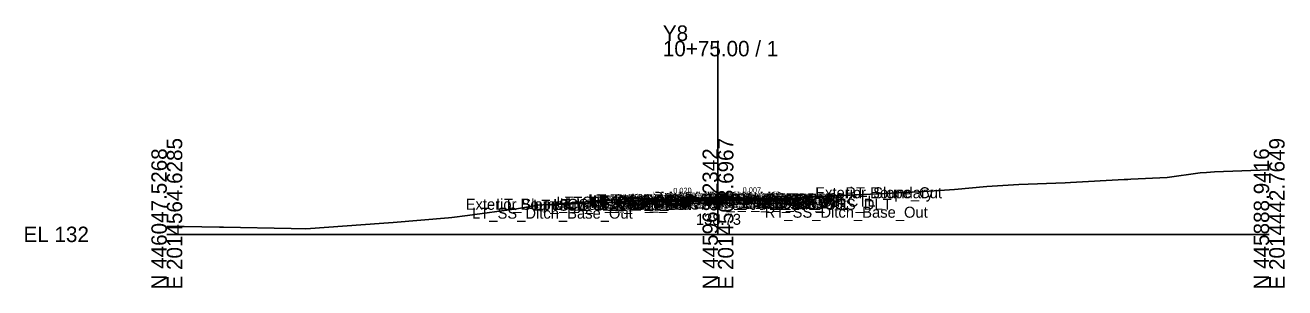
# Model space of a CAD drawing. Extents: x -26 to 1403, y -10 to 8043.
# Drawn here: x -25.7 to 202.8, y 1490.3 to 1537.9 of the extents above; entities that cross this region are included whole.
import ezdxf

# ---------------------------------------------------------------- set-up
doc = ezdxf.new("R2010")
doc.units = 0
for name, color, linetype in [('Default', 7, 'Continuous'), ('Exist CMT Pavement', 7, 'Continuous'), ('Exist Cross Section Cell', 7, 'Continuous'), ('Exist XS Center Line Elevation Label', 7, 'Continuous'), ('Exist XS Ground Line', 7, 'Continuous'), ('Prop CMT Pvmt Course 1', 7, 'Continuous'), ('Prop CMT Pvmt Course 2', 7, 'Continuous'), ('Prop CMT Pvmt Course 3', 7, 'Continuous'), ('Prop CMT Pvmt Surface', 7, 'Continuous'), ('Prop CMT Pvmt Surface Shoulder', 7, 'Continuous'), ('Prop CMT Pvmt Wedge Surface 1', 7, 'Continuous'), ('Prop CMT Pvmt Wedge Surface 2', 7, 'Continuous'), ('Prop CMT Pvmt Wedge Surface 3', 7, 'Continuous'), ('Prop CMT Shld Paved Course 1', 7, 'Continuous'), ('Prop CMT Shld Paved Course 2', 7, 'Continuous'), ('Prop CMT Shld Paved Course 3', 7, 'Continuous'), ('Prop CMT Slope Grass', 7, 'Continuous'), ('Prop CMT Subgrade Earthwork', 7, 'Continuous'), ('Prop XS Earthwork Shape', 7, 'Continuous'), ('Prop XS SE Text', 7, 'Continuous'), ('Scratch_Level_0', 7, 'Continuous')]:
    doc.layers.add(name, color=color, linetype=linetype)

msp = doc.modelspace()

# ---------------------------------------------------------------- linework, layer by layer
at = {"layer": 'Exist CMT Pavement'}
msp.add_lwpolyline([(89.09, 1506.27), (93.48, 1506.44), (100, 1506.73), (100.47, 1506.75), (108.36, 1506.51), (110.86, 1506.43)], dxfattribs=at)
at = {"layer": 'Exist Cross Section Cell'}
for p, q in [((100, 1500), (100, 1535.1)), ((0, 1500), (100, 1500)), ((100, 1500), (200, 1500))]:
    msp.add_line(p, q, dxfattribs=at)
at = {"layer": 'Exist XS Ground Line'}
msp.add_lwpolyline([(0, 1501.45), (3.18, 1501.42), (9.54, 1501.33), (10.31, 1501.32), (22.55, 1501.05), (25.21, 1500.99), (39.37, 1502.04), (41.09, 1502.15), (51.1, 1503), (51.73, 1503.09), (54.58, 1503.42), (63.47, 1504.63), (67.38, 1505.27), (75.95, 1505.89), (78.83, 1506.12), (80.74, 1506.23), (84.07, 1506.5), (86.2, 1506.44), (87.21, 1506.46), (88.1, 1506.47), (89.06, 1506.48), (89.09, 1506.27), (93.48, 1506.44), (100, 1506.73), (100.47, 1506.75), (108.36, 1506.51), (110.86, 1506.43), (112.44, 1506.52), (118.36, 1506.88), (122.64, 1507.05), (136.49, 1507.69), (142.92, 1508.12), (148.79, 1508.67), (154.59, 1509.05), (163.02, 1509.37), (163.95, 1509.39), (173.68, 1509.95), (174.36, 1509.98), (174.88, 1510.03), (181.49, 1510.31), (187.49, 1511.16), (188.62, 1511.21), (190.09, 1511.34), (200, 1511.7)], dxfattribs=at)
at = {"layer": 'Prop CMT Pvmt Course 1'}
for points in [[(100, 1506.58), (87.31, 1506.33)], [(87.31, 1506.33), (87.31, 1506.08)], [(87.31, 1506.08), (100, 1506.33)], [(100, 1506.58), (112.45, 1506.5)], [(100, 1506.58), (100, 1506.33)], [(112.45, 1506.25), (100, 1506.33)], [(112.45, 1506.5), (112.45, 1506.25)]]:
    msp.add_lwpolyline(points, dxfattribs=at)
at = {"layer": 'Prop CMT Pvmt Course 2'}
for points in [[(100, 1506.33), (87.31, 1506.08)], [(87.31, 1505.83), (100, 1506.08)], [(87.31, 1506.08), (87.31, 1505.83)], [(100, 1506.33), (112.45, 1506.25)], [(100, 1506.33), (100, 1506.08)], [(112.45, 1506), (100, 1506.08)], [(112.45, 1506.25), (112.45, 1506)]]:
    msp.add_lwpolyline(points, dxfattribs=at)
at = {"layer": 'Prop CMT Pvmt Course 3'}
for points in [[(100, 1506.08), (87.31, 1505.83)], [(100, 1506.08), (112.45, 1506)], [(100, 1506.08), (100, 1505.71)], [(87.31, 1505.83), (87.31, 1505.45)], [(87.31, 1505.45), (100, 1505.71)], [(112.45, 1505.62), (100, 1505.71)], [(112.45, 1506), (112.45, 1505.62)]]:
    msp.add_lwpolyline(points, dxfattribs=at)
at = {"layer": 'Prop CMT Pvmt Surface'}
for points in [[(100, 1506.58), (87.31, 1506.33)], [(100, 1506.58), (112.45, 1506.5)]]:
    msp.add_lwpolyline(points, dxfattribs=at)
at = {"layer": 'Prop CMT Pvmt Surface Shoulder'}
for points in [[(87.31, 1506.33), (87.31, 1506.33)], [(100, 1506.58), (100, 1506.58)], [(112.45, 1506.5), (112.45, 1506.5)]]:
    msp.add_lwpolyline(points, dxfattribs=at)
at = {"layer": 'Prop CMT Pvmt Wedge Surface 1'}
for points in [[(100, 1506.33), (87.31, 1506.08)], [(87.31, 1506.08), (87.31, 1506.33)], [(100, 1506.33), (112.45, 1506.25)], [(112.45, 1506.25), (112.45, 1506.5)]]:
    msp.add_lwpolyline(points, dxfattribs=at)
at = {"layer": 'Prop CMT Pvmt Wedge Surface 2'}
for points in [[(87.31, 1506.08), (87.31, 1506.33)], [(112.45, 1506.25), (112.45, 1506.5)]]:
    msp.add_lwpolyline(points, dxfattribs=at)
at = {"layer": 'Prop CMT Pvmt Wedge Surface 3'}
for points in [[(87.31, 1505.83), (87.31, 1506.33)], [(112.45, 1506), (112.45, 1506.5)]]:
    msp.add_lwpolyline(points, dxfattribs=at)
at = {"layer": 'Prop CMT Shld Paved Course 1'}
for points in [[(87.31, 1506.33), (87.06, 1506.07)], [(87.06, 1506.07), (87.31, 1506.08)], [(87.31, 1506.33), (87.31, 1506.33)], [(87.31, 1506.08), (87.31, 1506.33)], [(100, 1506.58), (100, 1506.58)], [(100, 1506.33), (100, 1506.58)], [(112.45, 1506.5), (112.45, 1506.5)], [(112.45, 1506.5), (112.7, 1506.24)], [(112.45, 1506.25), (112.45, 1506.5)], [(112.7, 1506.24), (112.45, 1506.25)]]:
    msp.add_lwpolyline(points, dxfattribs=at)
at = {"layer": 'Prop CMT Shld Paved Course 2'}
for points in [[(87.31, 1506.08), (87.06, 1506.07), (86.8, 1505.82)], [(87.31, 1505.83), (87.31, 1506.08)], [(100, 1506.08), (100, 1506.33)], [(112.45, 1506.25), (112.7, 1506.24), (112.96, 1505.99)], [(112.45, 1506), (112.45, 1506.25)], [(86.8, 1505.82), (87.31, 1505.83)], [(112.96, 1505.99), (112.45, 1506)]]:
    msp.add_lwpolyline(points, dxfattribs=at)
at = {"layer": 'Prop CMT Shld Paved Course 3'}
for points in [[(100, 1505.71), (100, 1506.08)], [(85.92, 1505.43), (87.31, 1505.45)], [(87.31, 1505.83), (86.8, 1505.82), (86.42, 1505.44)], [(87.31, 1505.45), (87.31, 1505.83)], [(112.45, 1505.62), (112.45, 1506)], [(112.45, 1506), (112.96, 1505.99), (113.34, 1505.61)], [(113.84, 1505.6), (112.45, 1505.62)]]:
    msp.add_lwpolyline(points, dxfattribs=at)
at = {"layer": 'Prop CMT Slope Grass'}
for p, q in [((112.45, 1506.5), (126.23, 1507.22)), ((81.31, 1505.85), (68.76, 1505.37))]:
    msp.add_line(p, q, dxfattribs=at)
msp.add_lwpolyline([(87.31, 1506.33), (81.31, 1505.85)], dxfattribs=at)
at = {"layer": 'Prop CMT Subgrade Earthwork'}
msp.add_line((114.87, 1506.63), (113.84, 1505.6), dxfattribs=at)
for points in [[(85.92, 1505.43), (81.31, 1505.85)], [(87.31, 1505.45), (85.92, 1505.43)], [(100, 1505.71), (87.31, 1505.45)], [(100, 1505.71), (112.45, 1505.62)], [(112.45, 1505.62), (113.84, 1505.6)]]:
    msp.add_lwpolyline(points, dxfattribs=at)
at = {"layer": 'Prop XS Earthwork Shape'}
for points in [[(89.09, 1506.27), (93.48, 1506.44), (93.79, 1506.46), (100, 1506.58), (107.62, 1506.53), (108.36, 1506.51), (110.86, 1506.43), (112.13, 1506.5), (118.36, 1506.88), (126.23, 1507.22), (114.87, 1506.63), (113.84, 1505.6), (112.45, 1505.62), (100, 1505.71), (87.31, 1505.45), (85.92, 1505.43), (81.31, 1505.85), (68.76, 1505.37), (75.95, 1505.89), (80.74, 1506.23), (84.07, 1506.5), (86.2, 1506.44), (87.21, 1506.46), (89.06, 1506.48)], [(89.09, 1506.27), (93.48, 1506.44), (93.79, 1506.46), (89.08, 1506.36)], [(100, 1506.58), (107.62, 1506.53), (100.47, 1506.75), (100, 1506.73), (93.79, 1506.46)], [(110.86, 1506.43), (112.13, 1506.5), (107.62, 1506.53), (108.36, 1506.51)]]:
    msp.add_lwpolyline(points, close=True, dxfattribs=at)

# ---------------------------------------------------------------- texts
at = {"layer": 'Default'}
msp.add_text('-', height=0.0001, dxfattribs=at).set_placement((0, 1500))
at = {"layer": 'Exist Cross Section Cell'}
for s, p in [('Y8', (90, 1535.1)), ('10+75.00 / 1', (90, 1532.3)), ('EL 132', (-26, 1498.6))]:
    msp.add_text(s, height=2.8, dxfattribs=at).set_placement(p)
for s, p in [('N 446047.5268', (0, 1490)), ('E 2014564.6285', (2.8, 1490)), ('N 445968.2342', (100, 1490)), ('E 2014503.6967', (102.8, 1490)), ('N 445888.9416', (200, 1490)), ('E 2014442.7649', (202.8, 1490))]:
    msp.add_text(s, height=2.8, rotation=90, dxfattribs=at).set_placement(p)
at = {"layer": 'Exist XS Center Line Elevation Label'}
msp.add_text('138.73', height=2, dxfattribs=at).set_placement((95.99, 1501.73))
at = {"layer": 'Prop XS SE Text'}
for s, rotation, p in [('0.020', 1.1458, (91.89, 1507.42)), ('0.007', 359.618, (104.47, 1507.55))]:
    msp.add_text(s, height=1, rotation=rotation, dxfattribs=at).set_placement(p)
at = {"layer": 'Scratch_Level_0'}
for s, p in [('Exterior Boundary', (117.65, 1506.55)), ('RT_Slope_Cut', (123.1, 1506.55)), ('Exterior Boundary', (54.22, 1504.46)), ('LT_Slope_Cut', (59.72, 1504.46)), ('LT_Sub_OSS_DLT', (66.47, 1504.29)), ('LT_Sub_Trench_Out', (70.12, 1504.43)), ('LT_GS_OS_CTL', (70.68, 1504.85)), ('LT_PS3_Shelf_Out', (72.28, 1504.81)), ('LT_Sub Tie Out', (76.43, 1505.27)), ('LT_PV_OEEOP_EG', (76.63, 1505.27)), ('LT_PS3_OEOP', (77.04, 1504.82)), ('LT_PS2_OEOP', (77.29, 1505.07)), ('LT_Sub_OEOT', (77.39, 1504.45)), ('LT_PV2_OEOT', (77.48, 1505.08)), ('LT_PV3_OEOT', (77.48, 1504.83)), ('LT_PV1_OEOT', (78.05, 1505.33)), ('LT_PS1_OEOP', (78.11, 1505.33)), ('LT_Sub_OEEOP', (78.3, 1504.49)), ('LT_PV2_OEEOP', (78.4, 1505.11)), ('LT_PV3_OEEOP', (78.4, 1504.86)), ('LT_PV1_OEEOP', (78.96, 1505.24)), ('RT_PV_IEEOP_EG', (88.14, 1505.73)), ('LT_PV_IEEOP_EG', (88.19, 1505.73)), ('RT_PV2_IEEOP', (89.91, 1505.33)), ('RT_PV3_IEEOP', (89.91, 1505.08)), ('LT_PV2_IEEOP', (89.95, 1505.33)), ('LT_PV3_IEEOP', (89.95, 1505.08)), ('RT_PV1_IEEOP', (90.47, 1505.46)), ('LT_PV1_IEEOP', (90.52, 1505.46)), ('PV2_PGL', (93.91, 1505.33)), ('PV1_PGL', (94.47, 1505.58)), ('RT_Sub_Trench_Out', (98, 1504.6)), ('RT_Sub Tie Out', (98.15, 1505.43)), ('RT_PV_OEEOP_EG', (98.36, 1505.43)), ('RT_PS3_Shelf_Out', (99.39, 1504.98)), ('RT_Sub_OEEOP', (100.03, 1504.64)), ('RT_PV2_OEEOP', (100.12, 1505.26)), ('RT_PV3_OEEOP', (100.12, 1505.01)), ('RT_PV1_OEEOP', (100.69, 1505.39)), ('RT_Sub_OEOT', (102.48, 1504.62)), ('RT_PV2_OEOT', (102.57, 1505.25)), ('RT_PV3_OEOT', (102.57, 1505)), ('RT_PS2_OEOP', (102.89, 1505.24)), ('RT_PV1_OEOT', (103.14, 1505.5)), ('RT_PS3_OEOP', (103.14, 1504.99)), ('RT_PS1_OEOP', (103.2, 1505.5)), ('RT_GS_OS_CTL', (107.77, 1505.02)), ('RT_Sub_OSS_DLT', (108.04, 1504.46)), ('LT_SS_Ditch_Base_Out', (55.39, 1502.85)), ('RT_SS_Ditch_Base_Out', (108.48, 1503.02))]:
    msp.add_text(s, height=2, dxfattribs=at).set_placement(p)

doc.saveas('drawing.dxf')
